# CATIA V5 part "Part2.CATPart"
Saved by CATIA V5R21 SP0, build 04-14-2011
Part number: Part2
Bounding box of the stored display mesh (mm): x -10.5 to 10.5, y 25 to 33, z 0 to 6
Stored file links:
  C:\Users\水心\Desktop\Arm_Detailed_Design_Assembly_Manu\CAD\Part2.CATPart
  C:\Users\水心\Desktop\Arm_Detailed_Design_Assembly_Manu\4Armbase.CATPart
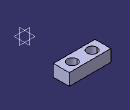
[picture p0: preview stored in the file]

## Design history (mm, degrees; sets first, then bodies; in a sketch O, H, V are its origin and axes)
Body1 (main body)
  Sketch1 on xy-plane, origin (0, 0, 0), H (1, 0, 0), V (0, 1, 0)
    line L1 (-10.5, 33) -> (10.5, 33)
    line L2 (10.5, 33) -> (10.5, 25)
    line L3 (10.5, 25) -> (-10.5, 25)
    line L4 (-10.5, 25) -> (-10.5, 33)
    circle A1 centre (5, 29) radius 2.5
    circle A2 centre (-5, 29) radius 2.5
    reference projected circle E1 centre (5, 29) radius 2.5
    reference projected circle E2 centre (-5, 29) radius 2.5
    reference projected line E3 (10.5, 25) -> (-10.5, 25)
    axis line L5 (51.9835, 4.75) -> (-25.6214, 4.75)
    length L2 = 8
    length L1 = 21
    distance V L2 = 10.5
    distance L5 L3 = 20.25
    horizontal: L1 H, L3 H, L5 H
    vertical: L2 V, L4 V
    coincidence: A1 E1, A2 E2, L3 E3
  Pad1: profile Sketch1, direction (0, 0, 1), length 6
